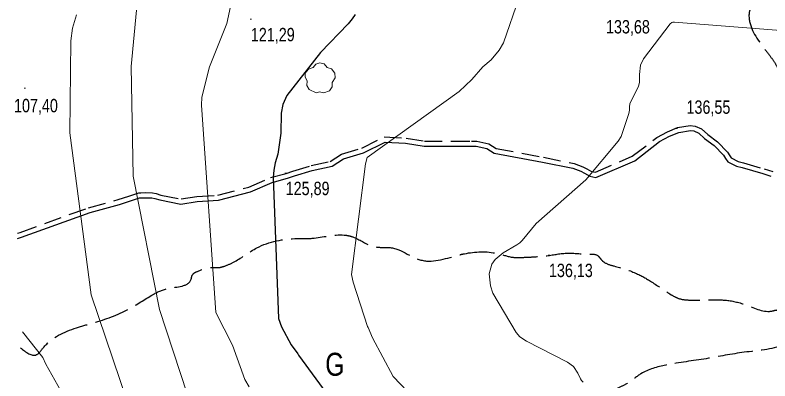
# Model space of a CAD drawing. Extents: x 483843 to 488449, y 4381269 to 4384483.
# Drawn here: x 484784.9 to 485277.5, y 4382213.1 to 4382451.9 of the extents above; entities that cross this region are included whole.
import ezdxf
from ezdxf.enums import TextEntityAlignment as Align

# ---------------------------------------------------------------- set-up
doc = ezdxf.new("R2010")
doc.units = 0
doc.header["$LTSCALE"] = 3.8
doc.linetypes.add('LONG_DASHED', pattern=[7.5, 6, -1.5])
doc.linetypes.add('MEDIUM_DASHED', pattern=[4.5, 3, -1.5])
for name, color, linetype, lineweight in [('29', 7, 'Continuous', 13), ('38', 7, 'Continuous', 25), ('7', 7, 'Continuous', 13), ('8', 7, 'Continuous', 25), ('9', 7, 'Continuous', 13)]:
    doc.layers.add(name, color=color, linetype=linetype, lineweight=lineweight)
doc.layers.add('31', color=7, linetype='Continuous')

msp = doc.modelspace()

# ---------------------------------------------------------------- linework, layer by layer
at = {"layer": '29'}
msp.add_lwpolyline([(484981.34, 4382401.23), (484976.8, 4382403.35), (484975.39, 4382405.89), (484975.49, 4382408.87), (484974.12, 4382411.28), (484974.16, 4382414.03), (484976.32, 4382416.63), (484979.51, 4382417.63), (484981.16, 4382419.82), (484983.73, 4382420.65), (484986.59, 4382420), (484988.54, 4382417.73), (484991.35, 4382416.91), (484993.48, 4382414.06), (484993.72, 4382410.93), (484991.84, 4382407.78), (484991.84, 4382405.1), (484990.02, 4382402.49), (484986.4, 4382401.15), (484983.63, 4382401.78)], close=True, dxfattribs=at)
at = {"layer": '38', "linetype": 'MEDIUM_DASHED'}
msp.add_lwpolyline([(484786.47, 4382309.46), (484788.12, 4382310.01), (484832.86, 4382326.12), (484852.22, 4382331.42), (484859.19, 4382333.63), (484861.13, 4382334.42), (484865.65, 4382335.8), (484866.93, 4382335.83), (484869.95, 4382335.96), (484874.52, 4382335.8), (484876.86, 4382335.46), (484880.12, 4382334.39), (484893.22, 4382331.88), (484903.46, 4382333.47), (484917.15, 4382334.32), (484937.36, 4382339.52), (484951.57, 4382345.78), (484961.75, 4382348.52), (484966.14, 4382350.09), (484978.05, 4382353.62), (484990.59, 4382356.38), (484997.84, 4382361.06), (485011.15, 4382365.06), (485025.77, 4382372.35), (485040.01, 4382371.54), (485052.11, 4382369.66), (485070.22, 4382369.54), (485082.83, 4382369.68), (485086.28, 4382369.51), (485093.97, 4382367.89), (485098.83, 4382364.9), (485129.72, 4382359.09), (485149.81, 4382355.01), (485155.33, 4382352.9), (485157.95, 4382351.58), (485161.06, 4382349.87), (485163.62, 4382349.32), (485187.64, 4382359.69), (485203.68, 4382372.04), (485210.67, 4382375.73), (485217.24, 4382378.44), (485225.56, 4382379.8), (485228.75, 4382379.46), (485232.88, 4382377.58), (485236.97, 4382373.92), (485243.37, 4382369.22), (485249.73, 4382362.42), (485251.3, 4382360.07), (485252.21, 4382358.66), (485256.76, 4382356.38), (485260.24, 4382355.48), (485273.76, 4382351.51), (485279.41, 4382349.72)], dxfattribs=at)
at = {"layer": '38'}
msp.add_lwpolyline([(484786.56, 4382306.04), (484789.19, 4382306.91), (484833.86, 4382322.98), (484853.14, 4382328.27), (484860.31, 4382330.53), (484862.24, 4382331.32), (484866.17, 4382332.54), (484867.03, 4382332.55), (484869.96, 4382332.68), (484874.22, 4382332.54), (484876.1, 4382332.25), (484879.29, 4382331.21), (484893.17, 4382328.54), (484903.82, 4382330.2), (484917.66, 4382331.06), (484938.44, 4382336.41), (484952.67, 4382342.68), (484962.73, 4382345.38), (484967.16, 4382346.97), (484978.87, 4382350.44), (484991.87, 4382353.29), (484999.23, 4382358.05), (485012.37, 4382362.01), (485026.44, 4382369.02), (485039.66, 4382368.27), (485051.85, 4382366.38), (485070.23, 4382366.26), (485082.78, 4382366.4), (485085.86, 4382366.24), (485092.73, 4382364.79), (485097.62, 4382361.79), (485129.1, 4382355.87), (485148.9, 4382351.86), (485154, 4382349.9), (485156.42, 4382348.68), (485159.9, 4382346.76), (485163.96, 4382345.89), (485189.31, 4382356.84), (485205.46, 4382369.27), (485212.06, 4382372.74), (485218.14, 4382375.26), (485225.65, 4382376.49), (485227.87, 4382376.25), (485231.06, 4382374.8), (485234.89, 4382371.37), (485241.19, 4382366.75), (485247.15, 4382360.37), (485248.55, 4382358.28), (485249.93, 4382356.13), (485255.6, 4382353.28), (485259.37, 4382352.32), (485272.8, 4382348.37), (485278.15, 4382346.68)], dxfattribs=at)
at = {"layer": '38', "linetype": 'LONG_DASHED'}
for points in [[(485265.32, 4382528.12), (485262.25, 4382527.69), (485255.47, 4382525.17), (485254.89, 4382523.66), (485269.37, 4382485.73), (485270.26, 4382474.04), (485269.81, 4382469.75), (485269.39, 4382467.95), (485268.83, 4382465.83), (485266.91, 4382459.65), (485264.37, 4382455.1), (485263.84, 4382451.11), (485273.12, 4382431.02), (485277.96, 4382424.65), (485281.43, 4382419.46), (485284.08, 4382414.33), (485286.1, 4382410.17), (485287.71, 4382395.64), (485288.35, 4382389.12), (485289.01, 4382385.76), (485289.32, 4382380.89), (485289.48, 4382376.39), (485290.67, 4382372.66), (485309.65, 4382359.94), (485317.23, 4382355.87), (485325.27, 4382351.06), (485330.26, 4382348.9), (485338.41, 4382346.05), (485345.68, 4382342.42), (485350.61, 4382339.66), (485355.39, 4382336.74), (485358.65, 4382334.63)], [(484788.33, 4382234.74), (484798.67, 4382230.05), (484803.24, 4382234.63), (484824.91, 4382247.7), (484836.04, 4382250.97), (484859.06, 4382259.93), (484874.65, 4382269.29), (484884.56, 4382273.37), (484899.83, 4382279.49), (484900.61, 4382282.21), (484903.87, 4382284.59), (484911.85, 4382286.98), (484915.45, 4382287.05), (484917.93, 4382287.09), (484921.74, 4382288.06), (484928.22, 4382290.95), (484942.69, 4382299.91), (484969.07, 4382306.01), (484978.82, 4382306.18), (484999.64, 4382308.28), (485005.36, 4382307.03), (485017.7, 4382301.17), (485026.64, 4382300.21), (485028.22, 4382300.23), (485050.5, 4382291.78), (485074.9, 4382295.36), (485078.11, 4382296.09), (485099.65, 4382296.25), (485110.05, 4382293.74), (485115.9, 4382293.69), (485123.47, 4382294.05), (485131.94, 4382294.8), (485145.49, 4382296.47), (485158.78, 4382295.88), (485165.4, 4382294.65), (485166.94, 4382292.8), (485169.07, 4382290.73), (485175.72, 4382288.08), (485189.84, 4382283.45), (485200.22, 4382277.78), (485213.12, 4382269.31), (485218.12, 4382266.85), (485223.91, 4382265.9), (485231.94, 4382265.82), (485237.5, 4382265.92), (485249.13, 4382265.67), (485262.09, 4382262.6), (485279.27, 4382258.78), (485280.83, 4382259.18), (485283.75, 4382259.46), (485294.77, 4382260.18), (485300.18, 4382259.83), (485305.78, 4382252.95), (485305.7, 4382249.2), (485305.14, 4382242.81)], [(485484.19, 4382224.31), (485462, 4382227.29), (485445.62, 4382228.8), (485425.21, 4382229.11), (485406, 4382229), (485396.4, 4382228.83), (485391.67, 4382228.82), (485385.88, 4382229.54), (485380.78, 4382229.6), (485373.58, 4382229.47), (485370.36, 4382229.19), (485363.41, 4382227.56), (485355.44, 4382223.9), (485352.32, 4382222.26), (485337.69, 4382222.15), (485331.36, 4382223.77), (485325.51, 4382227.71), (485318.96, 4382233.08), (485313.26, 4382237.4), (485311.13, 4382238.94), (485303.04, 4382242.7), (485286.78, 4382237), (485260.76, 4382231.74), (485235.93, 4382227.55), (485209.66, 4382223.4), (485193.33, 4382217.71), (485185.4, 4382212.09), (485179.16, 4382208.75), (485156.32, 4382197.92), (485147.1, 4382193.18), (485130.6, 4382184.18), (485114.63, 4382179.54), (485097.49, 4382172.64), (485085.86, 4382172.65), (485070.41, 4382172.45), (485061.41, 4382172.22), (485054.83, 4382171.13), (485047.82, 4382168.75), (485042.14, 4382163.02), (485025.23, 4382156.04), (485007.3, 4382147.7), (484996.93, 4382143.99), (484984.86, 4382143.85), (484972.93, 4382143.41), (484965.15, 4382142.37), (484941.34, 4382135.49), (484910.04, 4382127.36), (484902.35, 4382129.25), (484885.33, 4382158.51), (484879.28, 4382161.03), (484869.89, 4382165.81), (484839.61, 4382176.53), (484822.23, 4382174.87), (484818.62, 4382175.7), (484809.9, 4382176.45), (484809.97, 4382176.6), (484803.91, 4382175.74), (484793.66, 4382182.46), (484789.53, 4382186.8)]]:
    msp.add_spline(points, degree=3, dxfattribs=at)
at = {"layer": '7'}
for p, q in [((484938.26, 4382449.16), (484939.26, 4382449.16)), ((484790.72, 4382404.21), (484791.72, 4382404.21)), ((485216.25, 4382377.87), (485217.25, 4382377.87)), ((484960.98, 4382348.72), (484961.98, 4382348.72)), ((485132.78, 4382295.2), (485133.78, 4382295.2))]:
    msp.add_line(p, q, dxfattribs=at)
at = {"layer": '8'}
msp.add_lwpolyline([(485006.79, 4382452.3), (485004.95, 4382449.53), (485002.2, 4382446.09), (484984.19, 4382427.5), (484962.2, 4382399.37), (484959.72, 4382393.52), (484958.56, 4382387.87), (484958.25, 4382374.71), (484956.3, 4382361.01), (484954.7, 4382355.53), (484953.77, 4382350.64), (484953.38, 4382345.85), (484956.78, 4382253.86), (484958.66, 4382248.42), (484965.08, 4382236.63), (484969.35, 4382230.8), (484969.81, 4382229.94), (484990.14, 4382202.33)], dxfattribs=at)
at = {"layer": '9'}
for points in [[(485134.41, 4382522.89), (485103.68, 4382433.87), (485100.83, 4382428.93), (485095.49, 4382422.72), (485090.24, 4382418.03), (485082.99, 4382409.82), (485074.78, 4382402.06), (485014.64, 4382358.95), (485013.52, 4382354.86), (485004.5, 4382282.5), (485005.47, 4382277.58), (485014.89, 4382248.66), (485015.32, 4382247.89), (485018.1, 4382241.12), (485031.73, 4382215.88), (485109.71, 4382134.13)], [(484897.2, 4382204.51), (484879.05, 4382259.62), (484861.93, 4382346.74), (484860.74, 4382418.44), (484864.17, 4382455.16)], [(484937.59, 4382209.19), (484934.79, 4382214.08), (484926.83, 4382236.49), (484915.93, 4382257.62), (484906.45, 4382393.18), (484906.86, 4382398.28), (484911.75, 4382418.08), (484922.99, 4382446.4), (484925.58, 4382457.51)], [(484872.34, 4382157.31), (484834.58, 4382269.23), (484820.61, 4382375.09), (484821.2, 4382435.1), (484822.4, 4382443.37), (484824.94, 4382452.12)], [(485301.26, 4382440.43), (485215.2, 4382447.21), (485214.09, 4382447.19), (485213.78, 4382447.1), (485213.47, 4382446.96), (485212.38, 4382446.14), (485195, 4382423.26), (485193.09, 4382419.14), (485192.29, 4382413.17), (485192.38, 4382408.1), (485191.73, 4382405.25), (485186.82, 4382395.59), (485186.07, 4382393.87), (485185.83, 4382392.08), (485185.8, 4382389.9), (485185.34, 4382387.62), (485180.45, 4382372.69), (485178.42, 4382369.51), (485157.29, 4382344.24), (485124.88, 4382315.83), (485115.89, 4382304.83), (485114.33, 4382303.3), (485112.33, 4382301.9), (485103.45, 4382296.61), (485098.1, 4382292.23), (485097.02, 4382290.79), (485096.12, 4382289.25), (485094.3, 4382282.88), (485095.06, 4382275.2), (485096.72, 4382270.37), (485111.89, 4382244.61), (485114.29, 4382241.92), (485118.59, 4382239.06), (485145.42, 4382225.37), (485149.3, 4382222.55), (485152.24, 4382218.2), (485153.79, 4382214.36), (485154.64, 4382213.3), (485155.69, 4382212.24)], [(484789.67, 4382245.07), (484803.06, 4382228.26), (484804.94, 4382223.96), (484814.77, 4382206.47)]]:
    msp.add_lwpolyline(points, dxfattribs=at)

# ---------------------------------------------------------------- texts
at = {"layer": '31', "width": 0.8}
msp.add_text('G', height=15, dxfattribs=at).set_placement((484993.56, 4382216.41), align=Align.CENTER)
at = {"layer": '7', "width": 0.8}
for s, p in [('133,68', (485170.52, 4382439.89)), ('121,29', (484938.76, 4382434.79)), ('107,40', (484784.19, 4382388.43)), ('136,55', (485223.07, 4382387.44)), ('125,89', (484961.48, 4382334.35)), ('136,13', (485133.28, 4382280.83))]:
    msp.add_text(s, height=8.75, dxfattribs=at).set_placement(p)

doc.saveas('drawing.dxf')
